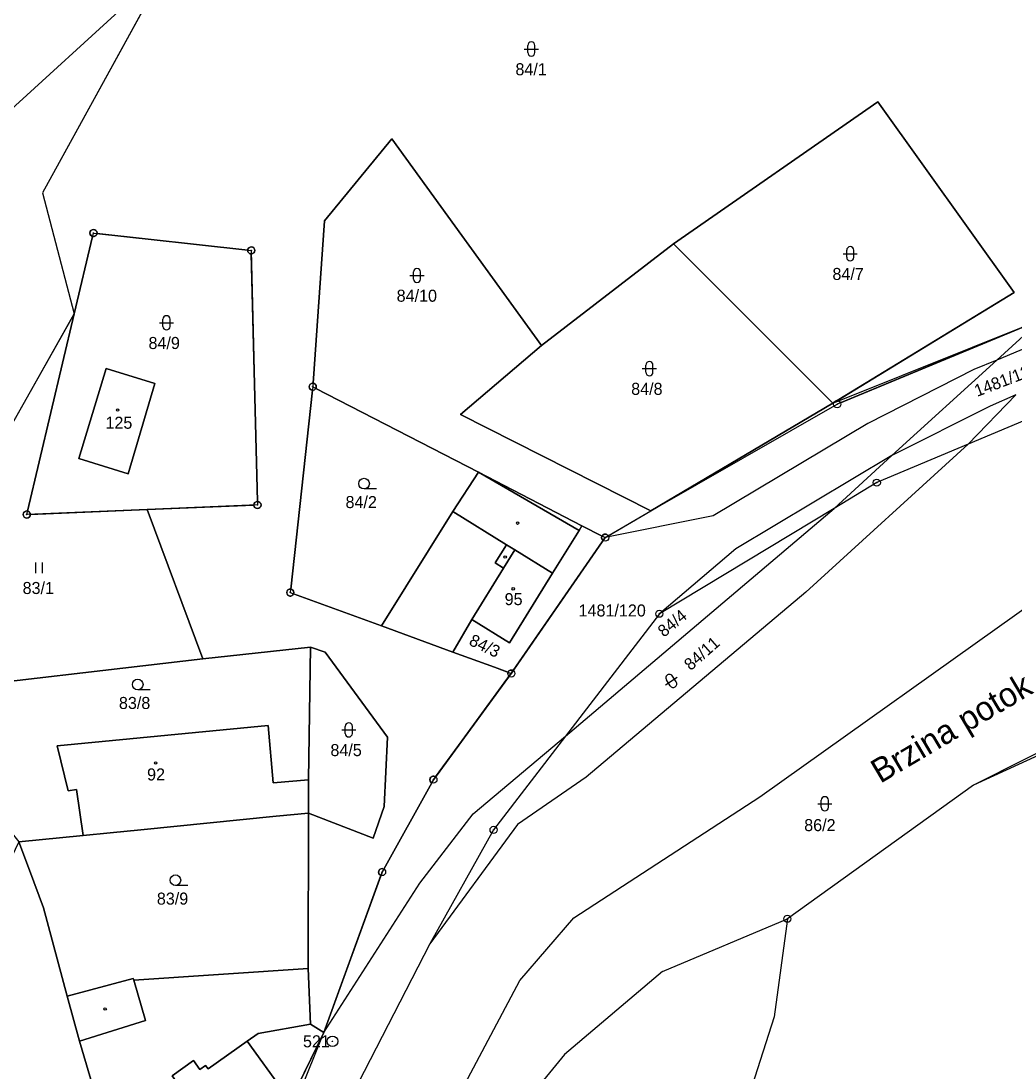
# Model space of a CAD drawing. Extents: x -760642 to -757221, y -1092371 to -1088855.
# Drawn here: x -758893.9 to -758753.7, y -1089681.5 to -1089533.4 of the extents above; entities that cross this region are included whole.
import ezdxf

# ---------------------------------------------------------------- set-up
doc = ezdxf.new("R2010")
doc.units = 0
for name, color, linetype in [('Vrstva 1', 7, 'Continuous'), ('Vrstva 13', 7, 'Continuous'), ('Vrstva 15', 7, 'Continuous'), ('Vrstva 17', 7, 'Continuous'), ('Vrstva 18', 7, 'Continuous'), ('Vrstva 19', 7, 'Continuous'), ('Vrstva 24', 7, 'Continuous'), ('Vrstva 25', 7, 'Continuous'), ('Vrstva 26', 7, 'Continuous'), ('Vrstva 27', 7, 'Continuous'), ('Vrstva 28', 7, 'Continuous'), ('Vrstva 4', 7, 'Continuous')]:
    doc.layers.add(name, color=color, linetype=linetype)

msp = doc.modelspace()

# ---------------------------------------------------------------- linework, layer by layer
at = {"layer": 'Vrstva 1'}
for p, q in [((-758896.88, -1089547.28), (-758873.48, -1089525.96)), ((-758873.48, -1089525.96), (-758890.87, -1089557.65)), ((-758801.87, -1089564.81), (-758773.06, -1089544.82)), ((-758773.06, -1089544.82), (-758753.83, -1089571.72)), ((-758841.57, -1089550.01), (-758851.09, -1089561.58)), ((-758841.57, -1089550.01), (-758820.49, -1089579.19)), ((-758890.87, -1089557.65), (-758886.37, -1089574.72)), ((-758851.09, -1089561.58), (-758852.74, -1089585)), ((-758886.37, -1089574.72), (-758883.67, -1089563.31)), ((-758883.67, -1089563.31), (-758861.42, -1089565.76)), ((-758861.42, -1089565.76), (-758860.54, -1089601.67)), ((-758820.49, -1089579.19), (-758801.87, -1089564.81)), ((-758801.87, -1089564.81), (-758779.37, -1089587.3)), ((-758753.83, -1089571.72), (-758779.37, -1089587.3)), ((-758911.24, -1089618.71), (-758886.37, -1089574.72)), ((-758893.08, -1089603.02), (-758886.37, -1089574.72)), ((-758749.97, -1089575.49), (-758778.78, -1089587.46)), ((-758749.97, -1089575.49), (-758756.26, -1089581.22)), ((-758820.49, -1089579.19), (-758831.91, -1089588.91)), ((-758756.26, -1089581.22), (-758771.05, -1089594.71)), ((-758885.75, -1089595.12), (-758881.89, -1089582.44)), ((-758881.89, -1089582.44), (-758875.01, -1089584.54)), ((-758875.01, -1089584.54), (-758878.79, -1089597.26)), ((-758852.74, -1089585), (-758855.91, -1089614.03)), ((-758852.74, -1089585), (-758829.38, -1089597.05)), ((-758753.57, -1089586.15), (-758760.31, -1089593.11)), ((-758779.37, -1089587.3), (-758805.07, -1089602.51)), ((-758805.07, -1089602.51), (-758778.78, -1089587.46)), ((-758831.91, -1089588.91), (-758805.07, -1089602.51)), ((-758751.45, -1089589.39), (-758760.31, -1089593.11)), ((-758783.21, -1089613.98), (-758760.31, -1089593.11)), ((-758760.31, -1089593.11), (-758773.19, -1089598.52)), ((-758878.79, -1089597.26), (-758885.75, -1089595.12)), ((-758771.05, -1089594.71), (-758779.21, -1089602.15)), ((-758789.7, -1089642.84), (-758723.95, -1089596.03)), ((-758833, -1089602.6), (-758829.38, -1089597.05)), ((-758829.38, -1089597.05), (-758814.77, -1089604.59)), ((-758773.19, -1089598.52), (-758779.21, -1089602.15)), ((-758876.09, -1089602.32), (-758893.08, -1089603.02)), ((-758860.54, -1089601.67), (-758876.09, -1089602.32)), ((-758876.09, -1089602.32), (-758868.25, -1089623.38)), ((-758833, -1089602.6), (-758843.05, -1089618.74)), ((-758817.1, -1089634.28), (-758779.21, -1089602.15)), ((-758811.5, -1089606.28), (-758805.07, -1089602.51)), ((-758779.21, -1089602.15), (-758803.86, -1089617.02)), ((-758815.19, -1089605.27), (-758818.92, -1089611.3)), ((-758814.77, -1089604.59), (-758815.19, -1089605.27)), ((-758814.77, -1089604.59), (-758811.5, -1089606.28)), ((-758811.5, -1089606.28), (-758824.74, -1089625.45)), ((-758818.92, -1089611.3), (-758825, -1089621.13)), ((-758855.91, -1089614.03), (-758843.05, -1089618.74)), ((-758783.21, -1089613.98), (-758814.18, -1089640.06)), ((-758803.86, -1089617.02), (-758817.1, -1089634.28)), ((-758843.05, -1089618.74), (-758833, -1089622.42)), ((-758830.32, -1089617.84), (-758833, -1089622.42)), ((-758825, -1089621.13), (-758830.32, -1089617.84)), ((-758853.04, -1089621.74), (-758868.25, -1089623.38)), ((-758853.04, -1089621.74), (-758853.36, -1089640.45)), ((-758853.04, -1089621.74), (-758851.01, -1089622.44)), ((-758868.25, -1089623.38), (-758908.57, -1089628.1)), ((-758851.01, -1089622.44), (-758842.22, -1089634.43)), ((-758833, -1089622.42), (-758827.13, -1089624.57)), ((-758827.13, -1089624.57), (-758824.74, -1089625.45)), ((-758824.74, -1089625.45), (-758835.72, -1089640.42)), ((-758859.04, -1089632.76), (-758888.77, -1089635.66)), ((-758859.04, -1089632.76), (-758858.31, -1089640.89)), ((-758842.22, -1089634.43), (-758842.67, -1089644.21)), ((-758830.12, -1089645.25), (-758817.1, -1089634.28)), ((-758817.1, -1089634.28), (-758827.24, -1089647.5)), ((-758888.77, -1089635.66), (-758887.23, -1089641.98)), ((-758853.36, -1089640.45), (-758858.31, -1089640.89)), ((-758853.36, -1089640.45), (-758853.32, -1089645.15)), ((-758835.72, -1089640.42), (-758842.96, -1089653.46)), ((-758814.18, -1089640.06), (-758823.86, -1089646.76)), ((-758887.23, -1089641.98), (-758886.06, -1089641.81)), ((-758886.06, -1089641.81), (-758885.12, -1089648.28)), ((-758815.93, -1089659.89), (-758789.7, -1089642.84)), ((-758842.67, -1089644.21), (-758844.21, -1089648.67)), ((-758857.9, -1089645.56), (-758876.99, -1089647.52)), ((-758857.9, -1089645.56), (-758853.32, -1089645.15)), ((-758853.39, -1089667.08), (-758853.32, -1089645.15)), ((-758844.21, -1089648.67), (-758853.32, -1089645.15)), ((-758837.65, -1089655), (-758830.12, -1089645.25)), ((-758823.86, -1089646.76), (-758836.23, -1089663.58)), ((-758885.12, -1089648.28), (-758894.2, -1089649.19)), ((-758881.31, -1089647.9), (-758885.12, -1089648.28)), ((-758876.99, -1089647.52), (-758881.31, -1089647.9)), ((-758827.24, -1089647.5), (-758836.23, -1089663.58)), ((-758894.2, -1089649.19), (-758892.71, -1089653.18)), ((-758892.71, -1089653.18), (-758890.72, -1089658.51)), ((-758842.96, -1089653.46), (-758851.17, -1089676.07)), ((-758851.17, -1089676.07), (-758837.65, -1089655)), ((-758890.72, -1089658.51), (-758887.39, -1089670.98)), ((-758823.54, -1089668.77), (-758815.93, -1089659.89)), ((-758803.41, -1089667.47), (-758785.8, -1089660.04)), ((-758836.23, -1089663.58), (-758851.99, -1089694.25)), ((-758853.39, -1089667.08), (-758877.98, -1089668.72)), ((-758853.39, -1089667.08), (-758853.08, -1089674.92)), ((-758803.41, -1089667.47), (-758817.26, -1089679.2)), ((-758887.39, -1089670.98), (-758878.05, -1089668.49)), ((-758878.05, -1089668.49), (-758877.98, -1089668.72)), ((-758846.04, -1089711.19), (-758823.54, -1089668.77)), ((-758885.64, -1089677.33), (-758887.39, -1089670.98)), ((-758860.46, -1089676.21), (-758853.08, -1089674.92)), ((-758853.08, -1089674.92), (-758851.17, -1089676.07)), ((-758851.17, -1089676.07), (-758869.61, -1089713.9)), ((-758862.67, -1089704.66), (-758851.17, -1089676.07)), ((-758862.01, -1089677.31), (-758860.46, -1089676.21)), ((-758885.64, -1089677.33), (-758884.05, -1089682.7)), ((-758862.01, -1089677.31), (-758856.94, -1089684.25)), ((-758817.26, -1089679.2), (-758822.82, -1089686.02))]:
    msp.add_line(p, q, dxfattribs=at)
at = {"layer": 'Vrstva 13'}
for p, q in [((-758747.26, -1089635.53), (-758759.55, -1089641.2)), ((-758759.55, -1089641.2), (-758785.8, -1089660.04)), ((-758785.8, -1089660.04), (-758787.66, -1089673.88)), ((-758787.66, -1089673.88), (-758793.98, -1089693.51))]:
    msp.add_line(p, q, dxfattribs=at)
at = {"layer": 'Vrstva 24'}
for centre, radius in [((-758883.67, -1089563.31), 0.5), ((-758883.67, -1089563.31), 0.0327), ((-758861.42, -1089565.76), 0.5), ((-758861.42, -1089565.76), 0.0327), ((-758852.74, -1089585), 0.5), ((-758852.74, -1089585), 0.0327), ((-758778.78, -1089587.46), 0.5), ((-758778.78, -1089587.46), 0.0327), ((-758773.19, -1089598.52), 0.5), ((-758773.19, -1089598.52), 0.0327), ((-758860.54, -1089601.67), 0.5), ((-758893.08, -1089603.02), 0.5), ((-758860.54, -1089601.67), 0.0327), ((-758893.08, -1089603.02), 0.0327), ((-758811.5, -1089606.28), 0.5), ((-758811.5, -1089606.28), 0.0327), ((-758855.91, -1089614.03), 0.5), ((-758855.91, -1089614.03), 0.0327), ((-758803.86, -1089617.02), 0.5), ((-758803.86, -1089617.02), 0.0327), ((-758824.74, -1089625.45), 0.5), ((-758824.74, -1089625.45), 0.0327), ((-758835.72, -1089640.42), 0.5), ((-758835.72, -1089640.42), 0.0327), ((-758827.24, -1089647.5), 0.5), ((-758827.24, -1089647.5), 0.0327), ((-758842.96, -1089653.46), 0.5), ((-758842.96, -1089653.46), 0.0327), ((-758785.8, -1089660.04), 0.5), ((-758785.8, -1089660.04), 0.0327), ((-758849.96, -1089677.33), 0.75), ((-758849.96, -1089677.33), 0.0327)]:
    msp.add_circle(centre, radius, dxfattribs=at)
at = {"layer": 'Vrstva 25'}
for p, q in [((-758822.92, -1089537.35), (-758820.92, -1089537.35)), ((-758822.42, -1089537.85), (-758822.42, -1089536.85)), ((-758821.42, -1089537.85), (-758821.42, -1089536.85)), ((-758777.44, -1089566.73), (-758777.44, -1089565.73)), ((-758776.44, -1089566.73), (-758776.44, -1089565.73)), ((-758777.94, -1089566.23), (-758775.94, -1089566.23)), ((-758839.04, -1089569.3), (-758837.04, -1089569.3)), ((-758838.54, -1089569.8), (-758838.54, -1089568.8)), ((-758837.54, -1089569.8), (-758837.54, -1089568.8)), ((-758874.37, -1089575.97), (-758872.37, -1089575.97)), ((-758873.87, -1089576.47), (-758873.87, -1089575.47)), ((-758872.87, -1089576.47), (-758872.87, -1089575.47)), ((-758805.76, -1089582.94), (-758805.76, -1089581.94)), ((-758804.76, -1089582.94), (-758804.76, -1089581.94)), ((-758806.26, -1089582.44), (-758804.26, -1089582.44)), ((-758843.76, -1089599.41), (-758845.51, -1089599.41)), ((-758891.867, -1089609.795), (-758891.867, -1089611.295)), ((-758890.845, -1089611.295), (-758890.845, -1089609.795)), ((-758803.012, -1089627.03), (-758801.33, -1089625.948)), ((-758802.321, -1089627.18), (-758802.862, -1089626.339)), ((-758801.48, -1089626.639), (-758802.021, -1089625.798)), ((-758875.68, -1089627.75), (-758877.43, -1089627.75)), ((-758848.66, -1089633.4), (-758846.66, -1089633.4)), ((-758848.16, -1089633.9), (-758848.16, -1089632.9)), ((-758847.16, -1089633.9), (-758847.16, -1089632.9)), ((-758781.52, -1089643.82), (-758779.52, -1089643.82)), ((-758781.02, -1089644.32), (-758781.02, -1089643.32)), ((-758780.02, -1089644.32), (-758780.02, -1089643.32)), ((-758870.36, -1089655.35), (-758872.11, -1089655.35))]:
    msp.add_line(p, q, dxfattribs=at)
for centre, radius in [((-758880.26, -1089588.28), 0.175), ((-758845.51, -1089598.66), 0.75), ((-758823.85, -1089604.23), 0.175), ((-758825.6, -1089609.01), 0.175), ((-758824.47, -1089613.5), 0.175), ((-758877.43, -1089627), 0.75), ((-758874.9, -1089638.06), 0.175), ((-758872.11, -1089654.6), 0.75), ((-758882.03, -1089672.76), 0.175)]:
    msp.add_circle(centre, radius, dxfattribs=at)
for centre, start, end in [((-758821.92, -1089536.85), 0, 180), ((-758821.92, -1089537.85), 180, 0), ((-758776.94, -1089565.73), 0, 180), ((-758776.94, -1089566.73), 180, 0), ((-758838.04, -1089568.8), 0, 180), ((-758838.04, -1089569.8), 180, 0), ((-758873.37, -1089575.47), 0, 180), ((-758873.37, -1089576.47), 180, 0), ((-758805.26, -1089581.94), 0, 180), ((-758805.26, -1089582.94), 180, 0), ((-758802.441, -1089626.068), 32.73534, 212.73534), ((-758801.9, -1089626.909), 212.73534, 32.73534), ((-758847.66, -1089632.9), 0, 180), ((-758847.66, -1089633.9), 180, 0), ((-758780.52, -1089643.32), 0, 180), ((-758780.52, -1089644.32), 180, 0)]:
    msp.add_arc(centre, 0.5, start, end, dxfattribs=at)
at = {"layer": 'Vrstva 26'}
for points in [[(-758778.318, -1089587.268), (-758749.97, -1089575.49), (-758734.24, -1089564.01), (-758723.83, -1089546.57), (-758746.01, -1089530.03), (-758752.59, -1089525.27), (-758785.52, -1089503.26), (-758822.68, -1089496.65), (-758849.04, -1089508.7), (-758873.48, -1089525.96), (-758890.87, -1089557.65), (-758886.37, -1089574.72), (-758883.785, -1089563.797)], [(-758852.705, -1089584.501), (-758851.09, -1089561.58), (-758841.57, -1089550.01), (-758820.49, -1089579.19), (-758801.87, -1089564.81), (-758773.06, -1089544.82), (-758753.83, -1089571.72), (-758778.815, -1089586.961)], [(-758778.815, -1089586.961), (-758753.83, -1089571.72), (-758773.06, -1089544.82), (-758801.87, -1089564.81), (-758779.37, -1089587.3), (-758779.208, -1089587.201)], [(-758811.069, -1089606.027), (-758805.07, -1089602.51), (-758831.91, -1089588.91), (-758820.49, -1089579.19), (-758841.57, -1089550.01), (-758851.09, -1089561.58), (-758852.705, -1089584.501)], [(-758883.785, -1089563.797), (-758886.37, -1089574.72), (-758892.965, -1089602.533)], [(-758861.917, -1089565.705), (-758883.173, -1089563.365)], [(-758883.173, -1089563.365), (-758861.917, -1089565.705)], [(-758779.37, -1089587.3), (-758801.87, -1089564.81), (-758820.49, -1089579.19), (-758831.91, -1089588.91), (-758805.07, -1089602.51), (-758779.37, -1089587.3)], [(-758860.552, -1089601.17), (-758861.408, -1089566.26)], [(-758861.408, -1089566.26), (-758860.552, -1089601.17)], [(-758892.965, -1089602.533), (-758886.37, -1089574.72), (-758911.24, -1089618.71), (-758912.5, -1089622.33), (-758911.93, -1089623.15), (-758908.57, -1089628.1), (-758868.25, -1089623.38), (-758876.09, -1089602.32), (-758892.58, -1089602.999)], [(-758881.89, -1089582.44), (-758885.75, -1089595.12), (-758878.79, -1089597.26), (-758875.01, -1089584.54), (-758881.89, -1089582.44)], [(-758855.856, -1089613.533), (-758852.794, -1089585.497)], [(-758852.794, -1089585.497), (-758855.856, -1089613.533)], [(-758855.44, -1089614.202), (-758843.05, -1089618.74), (-758833, -1089602.6), (-758829.38, -1089597.05), (-758852.296, -1089585.229)], [(-758852.296, -1089585.229), (-758829.38, -1089597.05), (-758814.77, -1089604.59), (-758811.944, -1089606.05)], [(-758824.24, -1089608.02), (-758818.92, -1089611.3), (-758815.19, -1089605.27), (-758829.38, -1089597.05), (-758833, -1089602.6), (-758825.43, -1089607.28), (-758824.24, -1089608.02)], [(-758829.38, -1089597.05), (-758815.19, -1089605.27), (-758814.77, -1089604.59), (-758829.38, -1089597.05)], [(-758892.58, -1089602.999), (-758876.09, -1089602.32), (-758861.04, -1089601.691)], [(-758861.04, -1089601.691), (-758876.09, -1089602.32), (-758868.25, -1089623.38), (-758853.04, -1089621.74), (-758851.01, -1089622.44), (-758842.22, -1089634.43), (-758842.67, -1089644.21), (-758844.21, -1089648.67), (-758853.32, -1089645.15), (-758853.39, -1089667.08), (-758853.08, -1089674.92), (-758851.17, -1089676.07), (-758843.131, -1089653.93)], [(-758825.82, -1089610.57), (-758827.01, -1089609.84), (-758825.43, -1089607.28), (-758833, -1089602.6), (-758843.05, -1089618.74), (-758833, -1089622.42), (-758830.32, -1089617.84), (-758825.82, -1089610.57)], [(-758811.944, -1089606.05), (-758814.77, -1089604.59), (-758815.19, -1089605.27), (-758818.92, -1089611.3), (-758825, -1089621.13), (-758830.32, -1089617.84), (-758833, -1089622.42), (-758827.13, -1089624.57), (-758825.209, -1089625.277)], [(-758827.01, -1089609.84), (-758825.82, -1089610.57), (-758824.24, -1089608.02), (-758825.43, -1089607.28), (-758827.01, -1089609.84)], [(-758824.456, -1089625.039), (-758811.784, -1089606.691)], [(-758825.82, -1089610.57), (-758830.32, -1089617.84), (-758825, -1089621.13), (-758818.92, -1089611.3), (-758824.24, -1089608.02), (-758825.82, -1089610.57)], [(-758825.209, -1089625.277), (-758827.13, -1089624.57), (-758833, -1089622.42), (-758843.05, -1089618.74), (-758855.44, -1089614.202)], [(-758885.12, -1089648.28), (-758886.06, -1089641.81), (-758887.23, -1089641.98), (-758888.77, -1089635.66), (-758859.04, -1089632.76), (-758858.31, -1089640.89), (-758853.36, -1089640.45), (-758853.04, -1089621.74), (-758868.25, -1089623.38), (-758908.57, -1089628.1), (-758904.25, -1089634.52), (-758902.79, -1089636.72), (-758901.79, -1089638.23), (-758899.45, -1089641.9), (-758897.14, -1089645.53), (-758894.2, -1089649.19), (-758885.12, -1089648.28)], [(-758853.32, -1089645.15), (-758844.21, -1089648.67), (-758842.67, -1089644.21), (-758842.22, -1089634.43), (-758851.01, -1089622.44), (-758853.04, -1089621.74), (-758853.36, -1089640.45), (-758853.32, -1089645.15)], [(-758835.424, -1089640.017), (-758825.036, -1089625.853)], [(-758853.36, -1089640.45), (-758858.31, -1089640.89), (-758859.04, -1089632.76), (-758888.77, -1089635.66), (-758887.23, -1089641.98), (-758886.06, -1089641.81), (-758885.12, -1089648.28), (-758881.31, -1089647.9), (-758876.99, -1089647.52), (-758857.9, -1089645.56), (-758853.32, -1089645.15), (-758853.36, -1089640.45)], [(-758842.717, -1089653.023), (-758835.963, -1089640.857)], [(-758853.32, -1089645.15), (-758857.9, -1089645.56), (-758876.99, -1089647.52), (-758881.31, -1089647.9), (-758885.12, -1089648.28), (-758894.2, -1089649.19), (-758892.71, -1089653.18), (-758890.72, -1089658.51), (-758887.39, -1089670.98), (-758878.05, -1089668.49), (-758877.98, -1089668.72), (-758853.39, -1089667.08), (-758853.32, -1089645.15)], [(-758887.39, -1089670.98), (-758890.72, -1089658.51), (-758892.71, -1089653.18), (-758894.2, -1089649.19), (-758897.45, -1089655.89), (-758921.61, -1089707.71), (-758906.21, -1089715.23), (-758902.28, -1089709.47), (-758904.75, -1089707.78), (-758900.27, -1089701.19), (-758897.79, -1089702.88), (-758887.55, -1089687.84), (-758884.05, -1089682.7), (-758885.64, -1089677.33), (-758887.39, -1089670.98)], [(-758881.54, -1089691.15), (-758871.34, -1089683.92), (-758872.57, -1089682.19), (-758869.54, -1089680.04), (-758868.66, -1089681.29), (-758867.86, -1089680.72), (-758867.51, -1089681.21), (-758862.01, -1089677.31), (-758860.46, -1089676.21), (-758853.08, -1089674.92), (-758853.39, -1089667.08), (-758877.98, -1089668.72), (-758876.34, -1089674.39), (-758885.64, -1089677.33), (-758884.05, -1089682.7), (-758881.54, -1089691.15)], [(-758876.34, -1089674.39), (-758877.98, -1089668.72), (-758878.05, -1089668.49), (-758887.39, -1089670.98), (-758885.64, -1089677.33), (-758876.34, -1089674.39)], [(-758876.57, -1089698.16), (-758872.38, -1089702.46), (-758869.61, -1089713.9), (-758851.17, -1089676.07), (-758853.08, -1089674.92), (-758860.46, -1089676.21), (-758862.01, -1089677.31), (-758856.94, -1089684.25), (-758876.57, -1089698.16)], [(-758867.51, -1089681.21), (-758867.86, -1089680.72), (-758868.66, -1089681.29), (-758869.54, -1089680.04), (-758872.57, -1089682.19), (-758871.34, -1089683.92), (-758881.54, -1089691.15), (-758877.84, -1089696.37), (-758876.57, -1089698.16), (-758856.94, -1089684.25), (-758862.01, -1089677.31), (-758867.51, -1089681.21)]]:
    msp.add_lwpolyline(points, dxfattribs=at)
for centre, start, end in [((-758883.67, -1089563.31), 0, 180), ((-758883.67, -1089563.31), 180, 256.68673), ((-758883.67, -1089563.31), 256.68673, 353.71634), ((-758883.67, -1089563.31), 353.71634, 0), ((-758861.42, -1089565.76), 173.71634, 180), ((-758861.42, -1089565.76), 180, 271.40379), ((-758861.42, -1089565.76), 0, 173.71634), ((-758861.42, -1089565.76), 271.40379, 0), ((-758852.74, -1089585), 85.97002, 180), ((-758852.74, -1089585), 180, 263.76814), ((-758852.74, -1089585), 0, 85.97002), ((-758852.74, -1089585), 332.71355, 0), ((-758852.74, -1089585), 263.76814, 332.71355), ((-758778.78, -1089587.46), 93.96924, 148.79911), ((-758778.78, -1089587.46), 22.56194, 93.96924), ((-758860.54, -1089601.67), 91.40379, 180), ((-758860.54, -1089601.67), 0, 91.40379), ((-758893.08, -1089603.02), 76.66134, 180), ((-758893.08, -1089603.02), 2.35929, 76.66134), ((-758860.54, -1089601.67), 180, 182.39361), ((-758860.54, -1089601.67), 182.39361, 0), ((-758893.08, -1089603.02), 180, 0), ((-758893.08, -1089603.02), 0, 2.35929), ((-758811.5, -1089606.28), 30.3837, 152.66919), ((-758811.5, -1089606.28), 152.66919, 180), ((-758811.5, -1089606.28), 180, 235.36862), ((-758855.91, -1089614.03), 83.76814, 180), ((-758855.91, -1089614.03), 180, 339.88465), ((-758855.91, -1089614.03), 0, 83.76814), ((-758855.91, -1089614.03), 339.88465, 0), ((-758824.74, -1089625.45), 55.36862, 159.78625), ((-758824.74, -1089625.45), 159.78625, 180), ((-758824.74, -1089625.45), 180, 233.74118), ((-758835.72, -1089640.42), 53.74118, 180), ((-758835.72, -1089640.42), 180, 240.96032), ((-758842.96, -1089653.46), 60.96032, 180), ((-758842.96, -1089653.46), 180, 250.04335)]:
    msp.add_arc(centre, 0.5, start, end, dxfattribs=at)
at = {"layer": 'Vrstva 27'}
for points in [[(-758752.59, -1089525.27), (-758785.52, -1089503.26), (-758822.68, -1089496.65), (-758849.04, -1089508.7), (-758873.48, -1089525.96), (-758890.87, -1089557.65), (-758886.37, -1089574.72), (-758911.24, -1089618.71), (-758932.33, -1089605.15), (-758934.28, -1089610.09), (-758964.56, -1089686.74)], [(-758851.17, -1089676.07), (-758842.96, -1089653.46), (-758835.72, -1089640.42), (-758824.456, -1089625.039), (-758811.5, -1089606.28), (-758805.07, -1089602.51), (-758779.37, -1089587.3), (-758749.97, -1089575.49)]]:
    msp.add_lwpolyline(points, dxfattribs=at)
at = {"layer": 'Vrstva 28'}
msp.add_lwpolyline([(-758744.89, -1089633.82), (-758759.55, -1089641.2), (-758785.8, -1089660.04), (-758787.66, -1089673.88), (-758793.98, -1089693.51)], dxfattribs=at)
at = {"layer": 'Vrstva 4'}
for p, q in [((-758743.69, -1089575.95), (-758756.26, -1089581.22)), ((-758756.26, -1089581.22), (-758759.49, -1089582.58)), ((-758759.49, -1089582.58), (-758774.47, -1089590.19)), ((-758753.57, -1089586.15), (-758757.18, -1089587.74)), ((-758757.18, -1089587.74), (-758771.05, -1089594.71)), ((-758774.47, -1089590.19), (-758796.25, -1089603.18)), ((-758771.05, -1089594.71), (-758793.07, -1089607.85)), ((-758829.38, -1089597.05), (-758815.19, -1089605.27)), ((-758825.43, -1089607.28), (-758833, -1089602.6)), ((-758796.25, -1089603.18), (-758811.5, -1089606.28)), ((-758827.01, -1089609.84), (-758825.43, -1089607.28)), ((-758825.43, -1089607.28), (-758824.24, -1089608.02)), ((-758825.82, -1089610.57), (-758824.24, -1089608.02)), ((-758824.24, -1089608.02), (-758818.92, -1089611.3)), ((-758793.07, -1089607.85), (-758803.86, -1089617.02)), ((-758825.82, -1089610.57), (-758827.01, -1089609.84)), ((-758830.32, -1089617.84), (-758825.82, -1089610.57)), ((-758877.98, -1089668.72), (-758876.34, -1089674.39)), ((-758876.34, -1089674.39), (-758885.64, -1089677.33)), ((-758867.51, -1089681.21), (-758862.01, -1089677.31)), ((-758872.57, -1089682.19), (-758869.54, -1089680.04)), ((-758869.54, -1089680.04), (-758868.66, -1089681.29)), ((-758868.66, -1089681.29), (-758867.86, -1089680.72)), ((-758867.86, -1089680.72), (-758867.51, -1089681.21))]:
    msp.add_line(p, q, dxfattribs=at)

# ---------------------------------------------------------------- texts
at = {"layer": 'Vrstva 15'}
msp.add_text('Brzina potok', height=3.4, rotation=30.66057, dxfattribs=at).set_placement((-758772.7, -1089641.02))
at = {"layer": 'Vrstva 17'}
msp.add_text('521', height=1.7, dxfattribs=at).set_placement((-758854.121, -1089678.18))
at = {"layer": 'Vrstva 18'}
for s, p in [('84/1', (-758824.158, -1089541.05)), ('84/7', (-758779.449, -1089569.93)), ('84/10', (-758840.91, -1089573)), ('84/9', (-758875.91, -1089579.67)), ('84/8', (-758807.832, -1089586.14)), ('84/2', (-758848.12, -1089602.11)), ('83/1', (-758893.664, -1089614.23)), ('1481/120', (-758815.25, -1089617.4)), ('83/8', (-758880.08, -1089630.45)), ('84/5', (-758850.25, -1089637.1)), ('86/2', (-758783.43, -1089647.68)), ('83/9', (-758874.73, -1089658.05))]:
    msp.add_text(s, height=1.7, dxfattribs=at).set_placement(p)
for s, rotation, p in [('1481/121', 20.88576, (-758759.04, -1089586.43)), ('84/4', 39.51387, (-758803.215, -1089620.405)), ('84/3', 334.25604, (-758830.84, -1089621.34)), ('84/11', 41.29821, (-758799.452, -1089625.119))]:
    msp.add_text(s, height=1.7, rotation=rotation, dxfattribs=at).set_placement(p)
at = {"layer": 'Vrstva 19'}
for s, p in [('125', (-758881.98, -1089590.92)), ('95', (-758825.68, -1089615.8)), ('92', (-758876.11, -1089640.53))]:
    msp.add_text(s, height=1.7, dxfattribs=at).set_placement(p)

doc.saveas('drawing.dxf')
